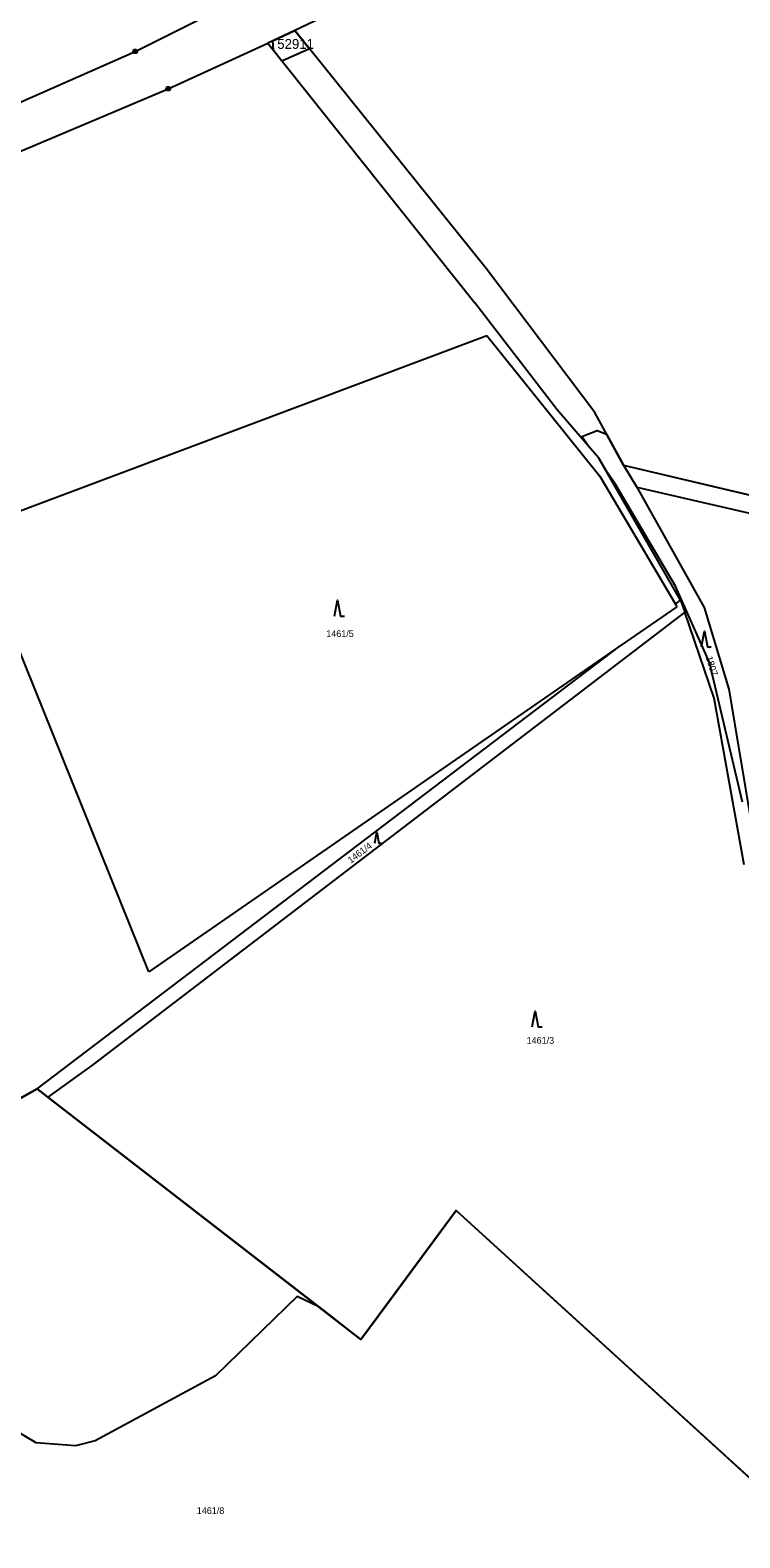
# Model space of a CAD drawing. Extents: x -779618 to -776429, y -1144546 to -1143350.
# Drawn here: x -778214.2 to -778034.7, y -1144103.8 to -1143722.3 of the extents above; entities that cross this region are included whole.
import ezdxf

# ---------------------------------------------------------------- set-up
doc = ezdxf.new("R2010")
doc.units = 0
for name, color, linetype in [('1', 7, 'Continuous'), ('11', 7, 'Continuous'), ('2', 7, 'Continuous'), ('3', 7, 'Continuous'), ('8', 7, 'Continuous')]:
    doc.layers.add(name, color=color, linetype=linetype)

msp = doc.modelspace()

# ---------------------------------------------------------------- linework, layer by layer
at = {"layer": '1'}
for p, q in [((-778187.65, -1143727.69), (-778162.69, -1143715.23)), ((-778147.27, -1143722.43), (-778154.14, -1143725.63)), ((-778140.87, -1143719.35), (-778147.27, -1143722.43)), ((-778098.92, -1143782.64), (-778147.27, -1143722.43)), ((-778179.34, -1143737.13), (-778154.14, -1143725.63)), ((-778154.14, -1143725.63), (-778101.8, -1143791.33)), ((-778255.89, -1143757.86), (-778187.65, -1143727.69)), ((-778262.61, -1143772.29), (-778179.34, -1143737.13)), ((-778071.39, -1143819.05), (-778098.92, -1143782.64)), ((-778080.96, -1143818.39), (-778101.8, -1143791.33)), ((-778229.36, -1143848.61), (-778098.73, -1143799.56)), ((-778098.73, -1143799.56), (-778070.15, -1143835.13)), ((-778070.41, -1143830.57), (-778080.96, -1143818.39)), ((-778064.15, -1143832.38), (-778071.39, -1143819.05)), ((-778049.75, -1143866.54), (-778070.41, -1143830.57)), ((-778064.15, -1143832.38), (-777897.94, -1143871.72)), ((-778064.15, -1143832.38), (-778060.8, -1143837.94)), ((-778070.15, -1143835.13), (-778051.04, -1143867.53)), ((-778060.8, -1143837.94), (-777884, -1143878.82)), ((-778060.8, -1143837.94), (-778043.76, -1143868.41)), ((-778184.19, -1143960.58), (-778229.36, -1143848.61)), ((-778051.04, -1143867.53), (-778049.75, -1143866.54)), ((-778051.04, -1143867.53), (-778050.65, -1143868.2)), ((-778049.75, -1143866.54), (-778048.61, -1143869.54)), ((-778048.61, -1143869.54), (-778198.33, -1143983.99)), ((-778050.65, -1143868.2), (-778064.97, -1143878.1)), ((-778041.2, -1143891.36), (-778048.61, -1143869.54)), ((-778043.76, -1143868.41), (-778037.53, -1143889.04)), ((-778212.5, -1143990.19), (-778064.97, -1143878.1)), ((-778064.97, -1143878.1), (-778184.19, -1143960.58)), ((-778037.53, -1143889.04), (-778029.28, -1143938.38)), ((-778033.63, -1143933.51), (-778041.2, -1143891.36)), ((-778198.33, -1143983.99), (-778209.77, -1143992.26)), ((-778212.5, -1143990.19), (-778230.79, -1144000.49)), ((-778209.77, -1143992.26), (-778212.5, -1143990.19)), ((-778130.59, -1144053.61), (-778209.77, -1143992.26)), ((-778106.47, -1144020.94), (-778130.59, -1144053.61)), ((-778015.68, -1144103.79), (-778106.47, -1144020.94))]:
    msp.add_line(p, q, dxfattribs=at)
at = {"layer": '11'}
msp.add_lwpolyline([(-778147.27, -1143722.43), (-778143.54, -1143727.08), (-778150.56, -1143730.12), (-778152.58, -1143727.58), (-778152.69, -1143727.32), (-778152.82, -1143725.02)], close=True, dxfattribs=at)
for points in [[(-778034.04, -1143917.62), (-778042.39, -1143882.33), (-778051.04, -1143862.96), (-778066.26, -1143837.08), (-778068.4, -1143834.07), (-778070.41, -1143830.57), (-778073.09, -1143827.47), (-778074.73, -1143825.17), (-778070.81, -1143823.6), (-778068.43, -1143824.5), (-778064.15, -1143832.38), (-778019.78, -1143842.88)], [(-778331.44, -1143918.51), (-778292.2, -1143949.58), (-778264.58, -1143975.57), (-778230.79, -1144000.49), (-778212.5, -1143990.19), (-778209.77, -1143992.26), (-778141.24, -1144045.35)], [(-778141.24, -1144045.35), (-778146.71, -1144042.75), (-778167.4, -1144062.76), (-778197.83, -1144079.22), (-778202.8, -1144080.49), (-778212.68, -1144079.78), (-778226.71, -1144071.46), (-778236.61, -1144062.32), (-778254.72, -1144032.96), (-778261.86, -1144027.66), (-778271.37, -1144024.15), (-778281.96, -1144025.02), (-778290.94, -1144032.02), (-778293.37, -1144040.75), (-778293.31, -1144049.15), (-778287.48, -1144065.65), (-778272.66, -1144086.7)], [(-778141.24, -1144045.35), (-778140.24, -1144046.13), (-778133.12, -1144051.65), (-778130.59, -1144053.61), (-778124.06, -1144044.76), (-778106.47, -1144020.94), (-778017.9, -1144101.76)]]:
    msp.add_lwpolyline(points, dxfattribs=at)
at = {"layer": '3'}
for points in [[(-778137.25, -1143870.57), (-778136.5, -1143866.57), (-778135.75, -1143870.57), (-778134.75, -1143870.57)], [(-778044.45, -1143878.37), (-778043.7, -1143874.37), (-778042.95, -1143878.37), (-778041.95, -1143878.37)], [(-778127.09, -1143928.01), (-778126.57, -1143925.21), (-778126.04, -1143928.01), (-778125.34, -1143928.01)], [(-778087.26, -1143974.53), (-778086.51, -1143970.53), (-778085.76, -1143974.53), (-778084.76, -1143974.53)]]:
    msp.add_lwpolyline(points, dxfattribs=at)
at = {"layer": '8'}
for p, q in [((-778187.77, -1143727.69), (-778187.53, -1143727.69)), ((-778179.46, -1143737.13), (-778179.22, -1143737.13))]:
    msp.add_line(p, q, dxfattribs=at)
for points in [[(-778187.5, -1143727.21), (-778187.25, -1143727.39), (-778187.15, -1143727.68), (-778187.25, -1143727.97), (-778187.5, -1143728.15), (-778187.81, -1143728.15), (-778188.06, -1143727.97), (-778188.16, -1143727.68), (-778188.06, -1143727.39), (-778187.81, -1143727.21)], [(-778179.19, -1143736.65), (-778178.94, -1143736.83), (-778178.84, -1143737.12), (-778178.94, -1143737.41), (-778179.19, -1143737.59), (-778179.5, -1143737.59), (-778179.75, -1143737.41), (-778179.85, -1143737.12), (-778179.75, -1143736.83), (-778179.5, -1143736.65)]]:
    msp.add_lwpolyline(points, close=True, dxfattribs=at)

# ---------------------------------------------------------------- texts
at = {"layer": '11'}
msp.add_text('52911', height=2.5, dxfattribs=at).set_placement((-778151.74, -1143727.05))
at = {"layer": '2'}
for s, p in [('1461/5', (-778139.34, -1143875.86)), ('1461/3', (-778088.66, -1143978.77)), ('1461/8', (-778172.09, -1144097.75))]:
    msp.add_text(s, height=1.7, dxfattribs=at).set_placement(p)
for s, rotation, p in [('1807', 287.3383, (-778043.37, -1143881.02)), ('1461/4', 37.185, (-778133.12, -1143933.23))]:
    msp.add_text(s, height=1.7, rotation=rotation, dxfattribs=at).set_placement(p)

doc.saveas('drawing.dxf')
